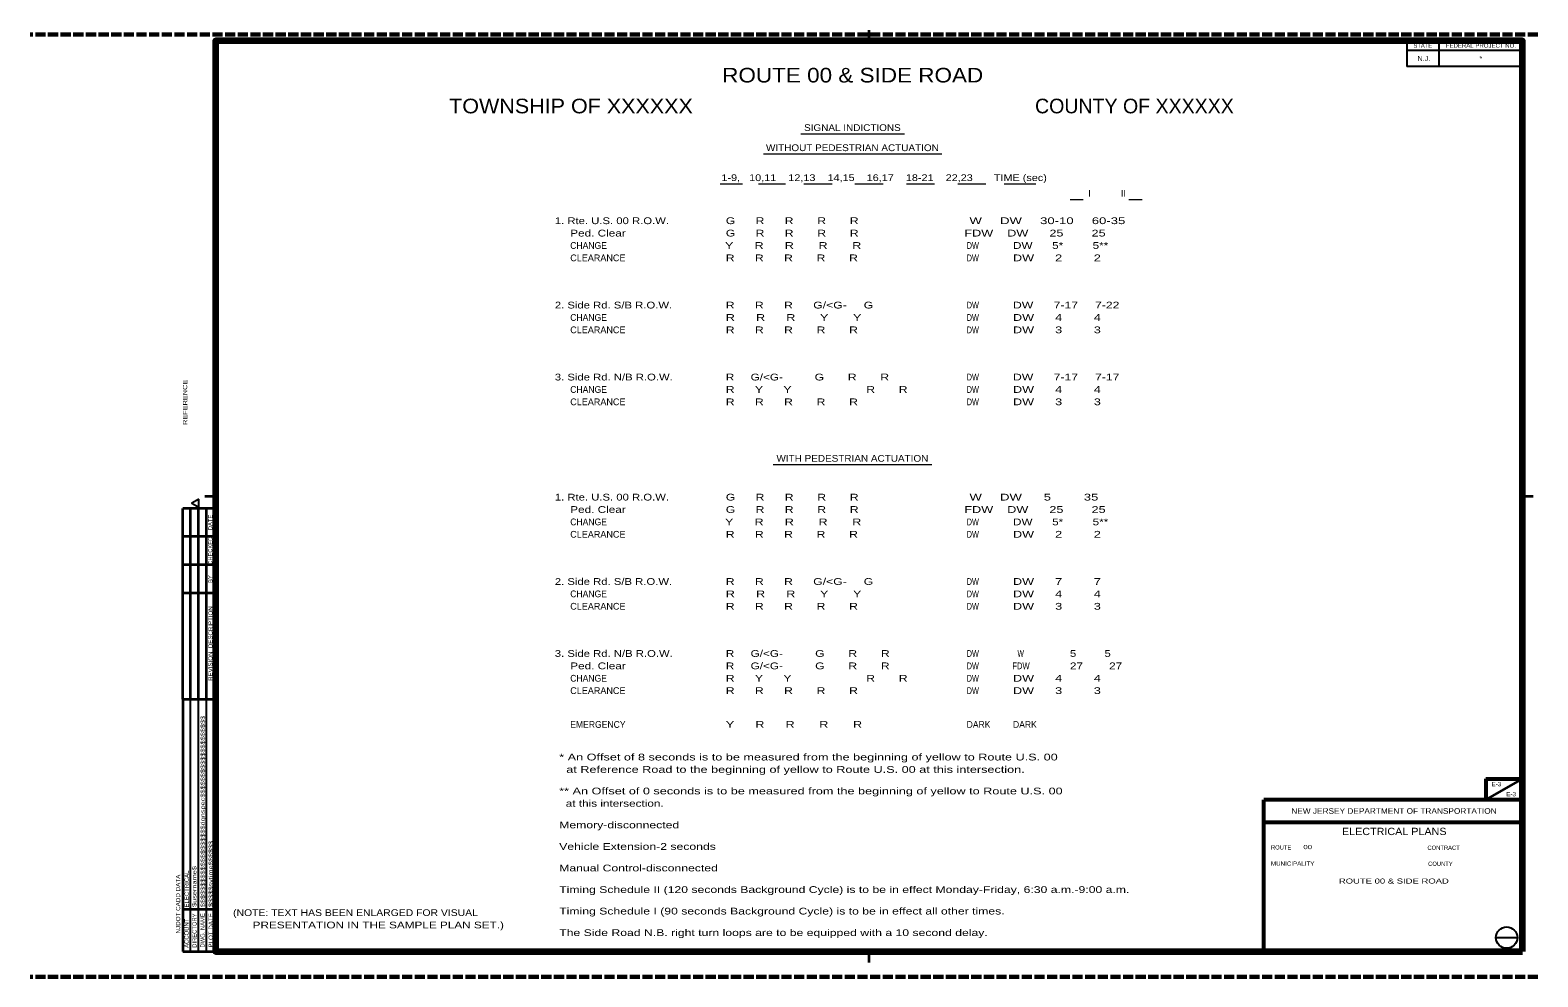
# Model space of a CAD drawing. Extents: x 168203 to 169864, y 223196 to 223870.
# Drawn here: x 169095.8 to 169364, y 223196.5 to 223364.9 of the extents above; entities that cross this region are included whole.
import ezdxf
from ezdxf.enums import TextEntityAlignment as Align

# ---------------------------------------------------------------- set-up
doc = ezdxf.new("R2010")
doc.units = 0
doc.header["$LTSCALE"] = 0.3
doc.linetypes.add('LONG_DASHED', pattern=[7.5, 6, -1.5])
doc.layers.add('1', color=7, linetype='Continuous', lineweight=13)
doc.layers.add('25', color=7, linetype='Continuous', lineweight=35)

msp = doc.modelspace()

# ---------------------------------------------------------------- linework, layer by layer
at = {"layer": '1', "linetype": 'LONG_DASHED', "lineweight": 60}
for p, q in [((169364.0333, 223364.1089), (169095.8093, 223364.1089)), ((169364.0333, 223196.4689), (169095.8093, 223196.4689))]:
    msp.add_line(p, q, dxfattribs=at)
at = {"layer": '1', "lineweight": 35}
for p, q in [((169245.0333, 223364.8589), (169245.0333, 223362.9689)), ((169126.8633, 223281.9689), (169128.7833, 223281.9689)), ((169361.2833, 223281.9689), (169363.2033, 223281.9689)), ((169122.946, 223245.8604), (169128.7833, 223245.8604)), ((169122.946, 223245.8604), (169122.946, 223200.9689)), ((169122.946, 223208.505), (169128.7833, 223208.505)), ((169122.946, 223200.9689), (169128.7833, 223200.9689)), ((169245.0333, 223200.9689), (169245.0333, 223199.0489))]:
    msp.add_line(p, q, dxfattribs=at)
at = {"layer": '1', "lineweight": 25}
for p, q in [((169340.7093, 223362.9689), (169340.7093, 223358.3969)), ((169361.2833, 223361.2544), (169340.7093, 223361.2544)), ((169346.4243, 223362.9689), (169346.4243, 223358.3969)), ((169361.2833, 223358.3969), (169340.7093, 223358.3969)), ((169124.3646, 223200.9689), (169124.3646, 223245.8604)), ((169125.7833, 223200.9689), (169125.7833, 223245.8604)), ((169127.1658, 223200.9689), (169127.1658, 223245.8604))]:
    msp.add_line(p, q, dxfattribs=at)
at = {"layer": '1'}
for p, q in [((169232.9075, 223346.4307), (169251.3817, 223346.4307)), ((169226.2774, 223342.8551), (169258.0118, 223342.8551)), ((169218.5477, 223337.5271), (169222.5417, 223337.5271)), ((169225.3687, 223337.5271), (169230.1789, 223337.5271)), ((169233.4202, 223337.5271), (169238.4994, 223337.5271)), ((169242.5427, 223337.5271), (169247.5348, 223337.5271)), ((169251.7296, 223337.5271), (169256.7245, 223337.5271)), ((169260.8566, 223337.5271), (169265.8572, 223337.5271)), ((169269.0681, 223337.5271), (169274.7201, 223337.5271)), ((169280.8095, 223334.7193), (169283.1467, 223334.7193)), ((169291.2843, 223334.7193), (169293.6215, 223334.7193)), ((169227.9711, 223287.6031), (169256.2091, 223287.6031))]:
    msp.add_line(p, q, dxfattribs=at)
at = {"layer": '1', "lineweight": 158}
msp.add_lwpolyline([(169361.2833, 223200.9689), (169361.2833, 223362.9689), (169128.7833, 223362.9689), (169128.7833, 223200.9689)], close=True, dxfattribs=at)
at = {"layer": '25'}
for p, q in [((169128.7833, 223279.8002), (169122.946, 223279.8002)), ((169122.946, 223245.8604), (169122.946, 223279.8002)), ((169124.3646, 223245.8604), (169124.3646, 223279.8002)), ((169125.7833, 223245.8604), (169125.7833, 223279.8002)), ((169127.1658, 223245.8604), (169127.1658, 223279.8002)), ((169128.7833, 223274.7671), (169122.946, 223274.7671)), ((169128.7833, 223269.7339), (169122.946, 223269.7339)), ((169128.7833, 223264.7008), (169122.946, 223264.7008)), ((169128.5845, 223264.7008), (169127.1658, 223264.7008)), ((169354.7833, 223227.9689), (169361.2833, 223231.7189))]:
    msp.add_line(p, q, dxfattribs=at)
at = {"layer": '25', "lineweight": 53}
for p, q in [((169354.7833, 223231.7189), (169361.2833, 223231.7189)), ((169354.7833, 223231.7189), (169354.7833, 223227.9689)), ((169315.2833, 223200.9689), (169315.2833, 223227.9689)), ((169361.2833, 223227.9689), (169315.2833, 223227.9689)), ((169315.2833, 223223.9689), (169361.2833, 223223.9689))]:
    msp.add_line(p, q, dxfattribs=at)
at = {"layer": '25', "lineweight": 25}
msp.add_line((169356.5733, 223203.4589), (169360.3833, 223203.4589), dxfattribs=at)
msp.add_lwpolyline([(169125.7923, 223281.4267), (169124.5725, 223280.7219), (169125.7923, 223280.0171)], close=True, dxfattribs=at)
msp.add_circle((169358.4841, 223203.4451), 1.9049, dxfattribs=at)

# ---------------------------------------------------------------- texts
at = {"layer": '1'}
for s, height, width, p in [('STATE', 0.7315, 1.05, (169343.5668, 223361.7459)), ('FEDERAL PROJECT NO.', 0.7315, 1.1, (169353.9028, 223361.7459)), ('ROUTE 00 & SIDE ROAD', 2.6, 1.15, (169242.1445, 223355.5529)), ('N.J.', 0.9144, 1.05, (169343.7648, 223359.3684)), ('TOWNSHIP OF XXXXXX', 2.6, 1.1, (169192.0279, 223350.0663)), ('SIGNAL INDICTIONS', 1.202, 1.1, (169242.0901, 223346.9191)), ('WITHOUT PEDESTRIAN ACTUATION', 1.202, 1.1, (169242.0901, 223343.3435)), ('WITH PEDESTRIAN ACTUATION', 1.202, 1.1, (169242.0901, 223288.0915))]:
    msp.add_text(s, height=height, dxfattribs=dict(at, width=width)).set_placement(p, align=Align.CENTER)
for s, height, p in [('*', 0.9144, (169353.9028, 223359.3599)), ('COUNTY OF XXXXXX', 2.6, (169292.2613, 223350.0663)), ('I            II', 1.202, (169287.4098, 223335.229))]:
    msp.add_text(s, height=height, dxfattribs=at).set_placement(p, align=Align.CENTER)
for s, width, p in [('1-9,   10,11    12,13    14,15    16,17    18-21    22,23       TIME (sec)', 1.2, (169218.7869, 223338.0155)), ('1. Rte. U.S. 00 R.O.W.', 1.25, (169189.1475, 223330.358)), ('G      R      R       R       R', 1.35, (169219.5657, 223330.358)), ('W     DW     30-10     60-35', 1.45, (169262.9244, 223330.358)), ('Ped. Clear', 1.3, (169191.8917, 223328.1562)), ('G      R      R       R       R', 1.35, (169219.5657, 223328.1562)), ('FDW    DW      25        25', 1.4, (169262.0098, 223328.1562)), ('CHANGE', 0.95, (169191.8917, 223325.9544)), ('Y      R      R       R       R', 1.4, (169219.4234, 223325.9544)), ('DW', 0.75, (169262.4156, 223325.9544)), ('DW      5*         5**', 1.3, (169270.659, 223325.9544)), ('R      R      R       R       R', 1.35, (169219.5657, 223323.7526)), ('DW', 0.75, (169262.4156, 223323.7526)), ('DW      2         2', 1.4, (169270.659, 223323.7526)), ('2. Side Rd. S/B R.O.W.', 1.25, (169189.1475, 223315.3522)), ('R      R      R      G/<G-     G', 1.35, (169219.5657, 223315.3522)), ('DW', 0.75, (169262.4156, 223315.3522)), ('DW      7-17     7-22', 1.35, (169270.659, 223315.3522)), ('CHANGE', 0.95, (169191.8917, 223313.1504)), ('R      R      R       Y       Y', 1.4, (169219.5657, 223313.1504)), ('DW', 0.75, (169262.4156, 223313.1504)), ('DW      4         4', 1.4, (169270.659, 223313.1504)), ('R      R      R       R       R', 1.35, (169219.5657, 223310.9486)), ('DW', 0.75, (169262.4156, 223310.9486)), ('DW      3         3', 1.4, (169270.659, 223310.9486)), ('3. Side Rd. N/B R.O.W.', 1.25, (169189.1475, 223302.5482)), ('R     G/<G-', 1.3, (169219.5657, 223302.5482)), ('G       R       R', 1.35, (169235.3664, 223302.5494)), ('DW', 0.75, (169262.4156, 223302.5482)), ('DW      7-17     7-17', 1.35, (169270.659, 223302.5482)), ('CHANGE', 0.95, (169191.8917, 223300.3464)), ('R      Y      Y', 1.35, (169219.5657, 223300.3464)), ('R      R      R       R       R', 1.35, (169219.5657, 223298.1446)), ('R       R', 1.35, (169244.5477, 223300.3464)), ('DW', 0.75, (169262.4156, 223300.3464)), ('DW', 0.75, (169262.4156, 223298.1446)), ('DW      4         4', 1.4, (169270.659, 223300.3464)), ('DW      3         3', 1.4, (169270.659, 223298.1446)), ('1. Rte. U.S. 00 R.O.W.', 1.25, (169189.1475, 223281.1929)), ('G      R      R       R       R', 1.35, (169219.5657, 223281.1929)), ('W     DW      5         35', 1.45, (169262.9244, 223281.1929)), ('CHANGE', 0.95, (169191.8917, 223276.7893)), ('Ped. Clear', 1.3, (169191.8917, 223278.9911)), ('Y      R      R       R       R', 1.4, (169219.4234, 223276.7893)), ('G      R      R       R       R', 1.35, (169219.5657, 223278.9911)), ('FDW    DW      25        25', 1.4, (169262.0098, 223278.9911)), ('DW', 0.75, (169262.4156, 223276.7893)), ('DW      5*         5**', 1.3, (169270.659, 223276.7893)), ('R      R      R       R       R', 1.35, (169219.5657, 223274.5875)), ('DW', 0.75, (169262.4156, 223274.5875)), ('DW      2         2', 1.4, (169270.659, 223274.5875)), ('2. Side Rd. S/B R.O.W.', 1.25, (169189.1475, 223266.1871)), ('R      R      R      G/<G-     G', 1.35, (169219.5657, 223266.1871)), ('DW', 0.75, (169262.4156, 223266.1871)), ('DW      7         7', 1.4, (169270.659, 223266.1871)), ('CHANGE', 0.95, (169191.8917, 223263.9853)), ('R      R      R       Y       Y', 1.4, (169219.5657, 223263.9853)), ('DW', 0.75, (169262.4156, 223263.9853)), ('DW      4         4', 1.4, (169270.659, 223263.9853)), ('R      R      R       R       R', 1.35, (169219.5657, 223261.7835)), ('DW', 0.75, (169262.4156, 223261.7835)), ('DW      3         3', 1.4, (169270.659, 223261.7835)), ('3. Side Rd. N/B R.O.W.', 1.25, (169189.1475, 223253.3831)), ('R     G/<G-', 1.3, (169219.5657, 223253.3831)), ('G       R       R', 1.35, (169235.4594, 223253.3826)), ('DW', 0.75, (169262.4156, 223253.3831)), ('W', 0.6, (169271.4591, 223253.3831)), ('5         5', 1.25, (169280.7938, 223253.3831)), ('Ped. Clear', 1.3, (169191.8917, 223251.1813)), ('R     G/<G-', 1.3, (169219.5657, 223251.1813)), ('G       R       R', 1.35, (169235.4594, 223251.1808)), ('DW', 0.75, (169262.4156, 223251.1813)), ('FDW', 0.85, (169270.5212, 223251.1813)), ('27        27', 1.3, (169280.7938, 223251.1813)), ('CHANGE', 0.95, (169191.8917, 223248.9795)), ('R      Y      Y', 1.35, (169219.5657, 223248.9795)), ('R       R', 1.35, (169244.5477, 223248.9795)), ('DW', 0.75, (169262.4156, 223248.9795)), ('DW      4         4', 1.4, (169270.659, 223248.9795)), ('R      R      R       R       R', 1.35, (169219.5657, 223246.7777)), ('DW', 0.75, (169262.4156, 223246.7777)), ('DW      3         3', 1.4, (169270.659, 223246.7777)), ('EMERGENCY', 0.95, (169191.8917, 223240.7623)), ('Y      R      R       R       R', 1.4, (169219.5657, 223240.7623)), ('DARK', 0.95, (169262.4156, 223240.7623)), ('DARK', 0.95, (169270.659, 223240.7623)), ('* An Offset of 8 seconds is to be measured from the beginning of yellow to Route U.S. 00', 1.4, (169189.9332, 223234.957)), ('  at Reference Road to the beginning of yellow to Route U.S. 00 at this intersection.', 1.4, (169189.9332, 223232.7552)), ('** An Offset of 0 seconds is to be measured from the beginning of yellow to Route U.S. 00', 1.4, (169189.9332, 223228.9226)), ('  at this intersection.', 1.3, (169189.9332, 223226.7208)), ('Memory-disconnected', 1.35, (169189.9332, 223222.8882)), ('Vehicle Extension-2 seconds', 1.35, (169189.9332, 223219.0556)), ('Manual Control-disconnected', 1.35, (169189.9332, 223215.223)), ('Timing Schedule II (120 seconds Background Cycle) is to be in effect Monday-Friday, 6:30 a.m.-9:00 a.m.', 1.35, (169189.9332, 223211.3904)), ('(NOTE: TEXT HAS BEEN ENLARGED FOR VISUAL', 1.15, (169131.9116, 223207.2864)), ('Timing Schedule I (90 seconds Background Cycle) is to be in effect all other times.', 1.35, (169189.9332, 223207.5578)), ('      PRESENTATION IN THE SAMPLE PLAN SET.)', 1.3, (169131.9116, 223205.0846)), ('The Side Road N.B. right turn loops are to be equipped with a 10 second delay.', 1.35, (169189.9332, 223203.7252))]:
    msp.add_text(s, height=1.202, dxfattribs=dict(at, width=width)).set_placement(p)
for p in [(169191.8917, 223323.7526), (169191.8917, 223310.9486), (169191.8917, 223298.1446), (169191.8917, 223274.5875), (169191.8917, 223261.7835), (169191.8917, 223246.7777)]:
    msp.add_text('CLEARANCE', height=1.202, dxfattribs=at).set_placement(p)
for s, height, width, p in [('REFERENCE                                                              ', 0.75, 1.3, (169123.7433, 223294.6289)), ('$$$$$$$$$$$$$$$$$$$$dgnspec$$$$$$$$$$$$$$$$$$$$', 0.7526, 1.3, (169126.8767, 223208.8484)), ('$$$$$sytime$$$$$$', 0.7526, 1.3, (169128.2953, 223208.8846)), ('$username$', 0.7526, 1.3, (169125.3947, 223208.8936)), ('NJDOT CADD DATA', 0.759, 1.1, (169122.5032, 223204.1677)), ('PLOT DATE', 0.7499, 1.1, (169128.3134, 223201.6737))]:
    msp.add_text(s, height=height, rotation=90, dxfattribs=dict(at, width=width)).set_placement(p)
for s, height, p in [('ELECTRICAL', 0.768, (169124.0393, 223208.8213)), ('ACCOUNT', 0.7589, (169124.0032, 223201.6285)), ('DIRECTORY', 0.75, (169125.4128, 223201.6376)), ('DWG. NAME', 0.75, (169126.8496, 223201.6828))]:
    msp.add_text(s, height=height, rotation=90, dxfattribs=at).set_placement(p)
at = {"layer": '25'}
msp.add_text('DATE', height=0.741, rotation=90, dxfattribs=at).set_placement((169128.214, 223277.2902), align=Align.CENTER)
for s, width, p in [('CHECKED', 0.9, (169128.214, 223272.2564)), ('BY', 0.9, (169128.214, 223267.2199)), ('REVISION  DESCRIPTION', 1.1, (169128.2502, 223255.7491))]:
    msp.add_text(s, height=0.741, rotation=90, dxfattribs=dict(at, width=width)).set_placement(p, align=Align.CENTER)
for s, height, width, p in [('E-3', 0.75, 1.1, (169356.6606, 223230.3729)), ('E-3', 0.75, 1.1, (169359.2798, 223228.5835)), ('NEW JERSEY DEPARTMENT OF TRANSPORTATION', 1, 1.1, (169338.4408, 223225.4689)), ('ELECTRICAL PLANS', 1.3, 1.1, (169338.488, 223221.6856)), ('             ROUTE 00 & SIDE ROAD            ', 0.9, 1.4, (169338.181, 223213.0589))]:
    msp.add_text(s, height=height, dxfattribs=dict(at, width=width)).set_placement(p, align=Align.CENTER)
for s, width, p in [('ROUTE', 0.95, (169316.5533, 223219.1189)), ('00                        ', 1.4, (169322.3133, 223219.1789)), ('MUNICIPALITY', 1.1, (169316.5533, 223216.2389))]:
    msp.add_text(s, height=0.75, dxfattribs=dict(at, width=width)).set_placement(p)
for s, p in [('CONTRACT', (169344.3933, 223219.0589)), ('COUNTY', (169344.5133, 223216.2089))]:
    msp.add_text(s, height=0.75, dxfattribs=at).set_placement(p)

doc.saveas('drawing.dxf')
